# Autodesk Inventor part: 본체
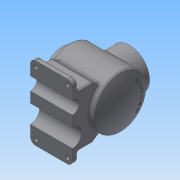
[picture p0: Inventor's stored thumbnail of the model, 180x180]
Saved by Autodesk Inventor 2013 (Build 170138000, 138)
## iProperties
Created: 2018-08
Part Number: 본체
Material: 일반
Document SubType Name: Modeling
Designer: Administrator
Density: 1 g/cm^3
Author: Administrator
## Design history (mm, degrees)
sketch "스케치1"
  geometry: L1 (0, 0)-(326.504, 0); L2 (0, 0)-(0, 38); L3 (0, 38)-(12, 38); L4 (12, 38)-(12, 50); L5 (12, 50)-(108.671, 50); A1 r 116 centre (4, 0) between (120, 0) and (108.671, 50)
  constraints: 10 end point, 3 perpendicular, 2 point on circle, 2 point on line, 1 centre point, 1 horizontal, 1 parallel
  dimensions: "d0" = 76 diameter of L3 L1; "d3" = 100 diameter of L5 L1; "d4" = 116 radius of A1; "d5" = 12 distance between parallel lines of L4 L2; "d6" = 108 horizontal distance of A1.start L4.end
revolve "회전1" sketch "스케치1" stored, may be unused: angle "d7" = 90 deg
feature "쉘1" dims "d8" = 10
sketch "스케치3"
  geometry: 2 further points
  constraints: 1 vertical alignment
  dimensions: "d9" = 32.5 distance of point (0, 32.5) point (0, 0)
hole "구멍1" sketch "스케치3" at (0, 32.5) diameter "d10" = 3.242; stored, may be unused: countersink angle "d14" = 90 deg, drill point angle "d16" = 118 deg; dims "d11" = 8, "d12" = 4, "d13" = 2, "d15" = 10
node "작업 평면1"
sketch "스케치4"
  geometry: C1 r 38 at (-62, 0); 1 further point
  constraints: 1 centre point, 1 horizontal alignment
  dimensions: "d21" = 76 diameter of C1; "d22" = 62 distance of C1.centre point (0, 0)
extrude "돌출1" join sketch "스케치4" stored distance "d23" = 10; taper "d24" = 0 deg
hole "구멍2" diameter "d27" = 54; stored, may be unused: countersink angle "d31" = 90 deg, drill point angle "d33" = 118 deg; dims "d25" = 10, "d26" = 10, "d28" = 8, "d29" = 4, "d30" = 2, "d32" = 10
sketch "스케치6"
  geometry: C1 r 27 at (0, 0) reference; 2 further points
  constraints: 1 vertical alignment
  dimensions: "d34" = 32.5 distance of C1.centre point (0, 32.5)
hole "구멍3" sketch "스케치6" at (0, 32.5) diameter "d35" = 3.242; stored, may be unused: countersink angle "d39" = 90 deg, drill point angle "d41" = 118 deg; dims "d36" = 8, "d37" = 4, "d38" = 2, "d40" = 10
node "작업 평면2"
sketch "스케치7"
  geometry: L1 (20, 70)-(100, 70); L2 (100, 70)-(100, -70); L3 (100, -70)-(20, -70); L4 (20, -70)-(20, 70); L5 (12, -50)-(12, 50) reference; C1 r 27 at (62, 0) reference; 3 further points
  constraints: 8 end point, 2 midpoint, 2 parallel, 1 horizontal, 1 horizontal alignment, 1 perpendicular
  dimensions: "d46" = 80 distance of L2.end L3.end; "d47" = 140 distance of L1.end L2.end; "d90" = 8 distance between parallel lines of L4 L5
extrude "돌출2" join sketch "스케치7" distance "d48" = 10; taper "d49" = 0 deg
node "작업 평면3"
sketch "스케치8"
  geometry: L1 (32.496, 38)-(65, 38) reference; L2 (65, 38)-(65, 34.121) reference; L3 (65, 34.121)-(55, 34.121) reference; L4 (55, 34.121)-(54.026, 32.5) reference; L5 (54.026, 32.5)-(55, 30.879) reference; L6 (55, 30.879)-(65, 30.879) reference; L7 (65, 30.879)-(65, 27) reference; L8 (65, 27)-(29.513, 27) reference; L9 (29.513, -27)-(65, -27) reference; L10 (65, -27)-(65, -30.879) reference; L11 (65, -30.879)-(55, -30.879) reference; L12 (55, -30.879)-(54.026, -32.5) reference; L13 (54.026, -32.5)-(55, -34.121) reference; L14 (55, -34.121)-(65, -34.121) reference; L15 (65, -34.121)-(65, -38) reference; L16 (65, -38)-(32.496, -38) reference; L17 (-82, 70)-(-72, 70) reference; L18 (-72, 70)-(-72, -70) reference; L19 (-72, -70)-(-82, -70) reference; L20 (-82, -70)-(-82, 70) reference; L21 (-29.59, -40.304)-(-72, -70); L22 (-29.59, 40.304)-(-72, 70); A1 r 50 centre (0, 0) between (32.496, 38) and (32.496, -38) reference; A2 r 40 centre (0, 0) between (29.513, 27) and (29.513, -27) reference; 1 further point
  constraints: 4 end point, 2 point on circle
  dimensions: "d56" = 35 deg angle of L22 L17; "d57" = 35 deg angle of L19 L21
extrude "돌출3" join sketch "스케치8" distance "d60" = 38; taper "d61" = 0 deg; dims "d91" = 42, "d92" = 0
sketch "스케치9"
  geometry: L1 (0, 0)-(0, 10) reference; L2 (140, 0)-(140, 10) reference; L3 (0, 10)-(20, 10); L4 (20, 10)-(20, 38.563); L5 (29.696, 52.41)-(0, 10) reference; L6 (140, 10)-(110.304, 52.41) reference; L7 (140, 10)-(120, 10); L8 (120, 10)-(120, 38.563); 1 further point
  constraints: 8 end point, 4 perpendicular, 2 point on line
  dimensions: "d62" = 20 distance of L1.end L3.end; "d63" = 20 distance of L2.end L7.end
extrude "돌출4" cut sketch "스케치9" stored distance "d64" = 80; taper "d65" = 0 deg
sketch "스케치10"
  geometry: L1 (0, 0)-(140, 0) reference; L2 (0, 0)-(140, 0); C1 r 12.5 at (42.5, 0); C2 r 17.5 at (92.5, 0); C3 r 28 at (70, 82) reference; 1 further point
  constraints: 2 centre point, 2 end point, 2 point on line, 1 collinear
  dimensions: "d66" = 25 diameter of C1; "d67" = 17.5 radius of C2; "d68" = 27.5 horizontal distance of C1.centre point (70, 82); "d69" = 22.5 horizontal distance of point (70, 82) C2.centre
extrude "돌출5" cut sketch "스케치10" stored distance "d70" = 80; taper "d71" = 0 deg
fillet "모깎기1" dims "d72" = 10
fillet "모깎기4" dims "d75" = 3
fillet "모깎기2" dims "d73" = 3
fillet "모깎기3" dims "d74" = 3
chamfer "모따기1" distance "d76" = 1; stored, may be unused: second distance "d77" = 2, angle "d78" = 45 deg
node "작업 평면4"
sketch "스케치13"
  geometry: C1 r 32.5 at (0, 0); 1 further point
  constraints: 1 centre point, 1 coincident, 1 other
  dimensions: "d80" = 32.5 radius of C1
feature "엠보싱1" sketch "스케치13" dims "d0" = 76, "d3" = 100, "d4" = 116, "d5" = 12, "d6" = 108, "d81" = 0.5, "d82" = 0
sketch "스케치15"
  geometry: A1 r 10 centre (7, -7) between (-3, -7) and (7, -17) reference; A2 r 10 centre (67, -7) between (67, -17) and (77, -7) reference; A3 r 10 centre (67, 113) between (77, 113) and (67, 123) reference; A4 r 10 centre (7, 113) between (7, 123) and (-3, 113) reference; 5 further points
  constraints: 4 coincident
hole "구멍4" sketch "스케치15" at (7, 113), (67, 113), (67, -7), (7, -7) diameter "d83" = 8; stored, may be unused: countersink angle "d87" = 90 deg, drill point angle "d89" = 118 deg; dims "d84" = 8, "d85" = 4, "d86" = 2, "d88" = 10
node "솔리드1"
pattern_circular "원형 패턴1" dims angle "d18" = 360 deg
pattern_circular "원형 패턴2" dims angle "d43" = 360 deg
node "절단 모서리 투영1"
other parameters: "d20" = 65, "d45" = -82, "d50" = 62, "d79" = 256
